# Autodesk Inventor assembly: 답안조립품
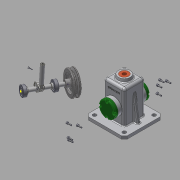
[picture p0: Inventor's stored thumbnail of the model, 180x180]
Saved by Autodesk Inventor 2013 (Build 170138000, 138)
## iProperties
Created: 2016-02
Part Number: 답안조립품
Document SubType Name: Assembly
Designer: user-11
Author: user-11
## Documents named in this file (16)
- C:\Users\user-11\Desktop\460211V1006\답안조립품.iam
- C:\Users\user-11\Desktop\460211V1006\V벨트풀리.ipt
- C:\Users\user-11\Desktop\460211V1006\고정핀 1.2 x 10.ipt
- C:\Users\user-11\Desktop\460211V1006\뒤커버.ipt
- C:\Users\user-11\Desktop\460211V1006\링크.ipt
- C:\Users\user-11\Desktop\460211V1006\멈춤나사 M3x8.ipt
- C:\Users\user-11\Desktop\460211V1006\베어링 12 x 32 x 10.ipt
- C:\Users\user-11\Desktop\460211V1006\본체.ipt
- C:\Users\user-11\Desktop\460211V1006\볼트 M4 x 12.ipt
- C:\Users\user-11\Desktop\460211V1006\부시.ipt
- C:\Users\user-11\Desktop\460211V1006\슬라이드.ipt
- C:\Users\user-11\Desktop\460211V1006\앞커버.ipt
- C:\Users\user-11\Desktop\460211V1006\오일실 12 25 7.ipt
- C:\Users\user-11\Desktop\460211V1006\키 4 x 4 x 10.ipt
- C:\Users\user-11\Desktop\460211V1006\편심축.ipt
- C:\Users\user-11\Desktop\460211V1006\핀 5 x 18.ipt
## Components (11 placed, 4 different names)
1. V벨트풀리:1
2. 고정핀 1.2 x 10:1
3. ISO 4762 M4 x 12:1
4. 핀 5 x 18:1
5. ISO 4762 M4 x 12:2
6. ISO 4762 M4 x 12:3
7. ISO 4762 M4 x 12:4
8. ISO 4762 M4 x 12:5
9. ISO 4762 M4 x 12:6
10. ISO 4762 M4 x 12:7
11. ISO 4762 M4 x 12:8
